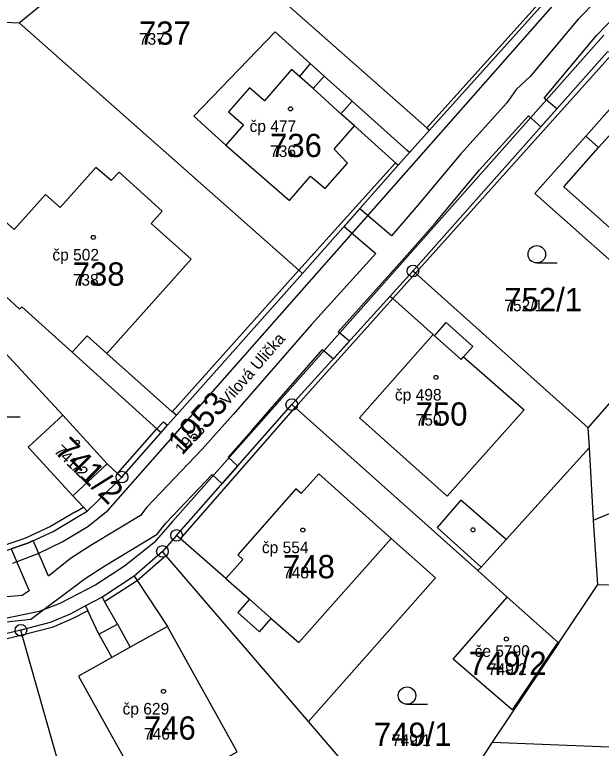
# Model space of a CAD drawing. Extents: x -763628 to -761565, y -976033 to -973833.
# Drawn here: x -762257.5 to -762207, y -974719.9 to -974656.7 of the extents above; entities that cross this region are included whole.
import ezdxf

# ---------------------------------------------------------------- set-up
doc = ezdxf.new("R2010")
doc.units = 0
for name, color, linetype in [('KN_cisla parcel 1000', 7, 'Continuous'), ('KN_cisla parcel 500', 7, 'Continuous'), ('KN_cisla popisna 500', 7, 'Continuous'), ('KN_hranice parcel', 7, 'Continuous'), ('KN_popisy', 7, 'Continuous'), ('KN_vecna bremena', 7, 'Continuous'), ('KN_vnitrni kresba parcel', 7, 'Continuous'), ('KN_znacky bodu BP', 7, 'Continuous'), ('KN_znacky budov', 7, 'Continuous'), ('KN_znacky kultur', 7, 'Continuous')]:
    doc.layers.add(name, color=color, linetype=linetype)

msp = doc.modelspace()

# ---------------------------------------------------------------- linework, layer by layer
at = {"layer": 'KN_hranice parcel'}
for p, q in [((-762257.09, -974657.45), (-762244.21, -974646.8)), ((-762262.51, -974657.17), (-762257.09, -974657.45)), ((-762223.51, -974668.61), (-762221.79, -974666.67)), ((-762224.46, -974669.69), (-762223.51, -974668.61)), ((-762232.71, -974679.01), (-762224.46, -974669.69)), ((-762243.56, -974691.22), (-762232.71, -974679.01)), ((-762208.11, -974692.29), (-762199.15, -974682.04)), ((-762243.54, -974701.56), (-762233.63, -974690.3)), ((-762248.24, -974696.54), (-762244.88, -974692.71)), ((-762207.28, -974705.78), (-762207.67, -974700.25)), ((-762243.54, -974701.56), (-762244.76, -974702.94)), ((-762210.64, -974710.82), (-762207.28, -974705.78)), ((-762207.28, -974705.78), (-762190.73, -974706.37)), ((-762215.08, -974706.87), (-762210.73, -974710.75)), ((-762210.64, -974710.82), (-762216.37, -974719.37)), ((-762210.73, -974710.75), (-762210.64, -974710.82)), ((-762222.55, -974728.78), (-762232.18, -974717.57)), ((-762216.37, -974719.37), (-762222.55, -974728.78))]:
    msp.add_line(p, q, dxfattribs=at)
for points in [[(-762221.79, -974666.67), (-762211.21, -974654.91), (-762212.34, -974651.01)], [(-762236.37, -974653.75), (-762222.01, -974666.48), (-762221.79, -974666.67)], [(-762257.09, -974657.45), (-762233.01, -974678.74), (-762232.71, -974679.01)], [(-762223.51, -974668.61), (-762223.73, -974668.41), (-762228.43, -974664.18), (-762230.84, -974662.02), (-762232.04, -974660.94), (-762235.06, -974658.22), (-762242.06, -974665.47), (-762239.3, -974667.96), (-762233.82, -974672.73), (-762232.01, -974670.63), (-762230.76, -974671.71), (-762228.82, -974669.51), (-762229.99, -974668.32), (-762228.23, -974666.3), (-762224.69, -974669.49), (-762224.46, -974669.69)], [(-762202.51, -974659.7), (-762206.5, -974659.96), (-762223.2, -974678.8)], [(-762202.51, -974659.7), (-762202.71, -974659.92), (-762203.96, -974661.32), (-762205.84, -974664.39), (-762208.32, -974667.18), (-762212.71, -974672.12), (-762202.76, -974680.97), (-762200.02, -974677.89)], [(-762243.56, -974691.22), (-762243.91, -974690.91), (-762249.55, -974685.91), (-762242.28, -974677.77), (-762245.72, -974674.71), (-762244.78, -974673.65), (-762248.49, -974670.3), (-762249.17, -974671.02), (-762250.48, -974669.9), (-762253.55, -974673.34), (-762254.82, -974672.21), (-762257.51, -974675.24), (-762260.52, -974672.57), (-762263.79, -974675.92), (-762260.66, -974678.79), (-762257.05, -974682.09), (-762256.85, -974681.88), (-762252.52, -974685.8), (-762245.23, -974692.4), (-762244.88, -974692.71)], [(-762273.2, -974675.16), (-762268.31, -974675.26), (-762267.98, -974675.4), (-762253.34, -974691.21)], [(-762223.2, -974678.8), (-762225.16, -974680.97), (-762233.63, -974690.3)], [(-762208.11, -974692.29), (-762222.97, -974679), (-762223.2, -974678.8)], [(-762207.67, -974700.25), (-762178.22, -974687.98), (-762177.79, -974687.84)], [(-762233.63, -974690.3), (-762233.33, -974690.56), (-762217.62, -974704.59), (-762215.08, -974706.87)], [(-762251.23, -974699.47), (-762251.56, -974699.12), (-762252.46, -974698.14), (-762256.32, -974693.97), (-762253.34, -974691.21)], [(-762253.34, -974691.21), (-762249.52, -974695.39), (-762248.63, -974696.22), (-762248.24, -974696.54)], [(-762244.88, -974692.71), (-762244.32, -974692.07), (-762243.56, -974691.22)], [(-762207.67, -974700.25), (-762208.01, -974694), (-762208.11, -974692.29)], [(-762232.18, -974717.57), (-762221.25, -974705.22), (-762225.07, -974701.83), (-762231.31, -974696.27), (-762232.81, -974697.95), (-762233.27, -974697.54), (-762238.28, -974703.23), (-762237.85, -974703.63), (-762239.31, -974705.27), (-762243.2, -974701.85), (-762243.54, -974701.56)], [(-762251.23, -974699.47), (-762250.26, -974698.54), (-762248.24, -974696.54)], [(-762274.8, -974704.07), (-762269.9, -974703.9), (-762268.41, -974703.84), (-762263.3, -974703.66), (-762260.93, -974703.38), (-762258.47, -974702.94), (-762256.33, -974702.23), (-762254.17, -974701.21), (-762252.01, -974699.93), (-762251.23, -974699.47)], [(-762244.76, -974702.94), (-762247.18, -974705.06), (-762249.63, -974706.69), (-762249.96, -974706.87), (-762251.37, -974707.63), (-762252.69, -974708.34), (-762254.43, -974709.06), (-762256.94, -974709.73)], [(-762232.18, -974717.57), (-762244.47, -974703.28), (-762244.76, -974702.94)], [(-762210.73, -974710.75), (-762214.65, -974716.57), (-762219.73, -974712.21), (-762215.08, -974706.87)], [(-762244.32, -974709.41), (-762247.53, -974711.19), (-762249.11, -974712.07), (-762251.98, -974713.67), (-762245.98, -974724.46), (-762238.32, -974720.18), (-762244.32, -974709.41)], [(-762256.94, -974709.73), (-762259.85, -974710.4), (-762261.07, -974710.45)], [(-762252.22, -974726.41), (-762256.82, -974710.15), (-762256.94, -974709.73)], [(-762216.37, -974719.37), (-762175.41, -974720.99), (-762174.98, -974721.01)]]:
    msp.add_lwpolyline(points, dxfattribs=at)
at = {"layer": 'KN_vecna bremena'}
for points in [[(-762207.35, -974655.42), (-762208.99, -974657.12), (-762213.1, -974662.05), (-762214.33, -974663.17), (-762215.13, -974664.33), (-762219.08, -974668.71), (-762222.91, -974673.31), (-762225.05, -974675.76), (-762227.78, -974673.44), (-762229.13, -974674.97), (-762226.4, -974677.28), (-762231.93, -974683.41), (-762238.68, -974691.14), (-762241.33, -974694.14), (-762246.09, -974699.13), (-762246.64, -974699.84), (-762250.83, -974702.37), (-762252.66, -974703.56), (-762254.56, -974705.07), (-762255.87, -974702.01), (-762256.33, -974702.23), (-762257.79, -974702.72), (-762256.24, -974706.32), (-762256.83, -974706.72), (-762265.28, -974707.45)], [(-762262.17, -974709.44), (-762256.09, -974708.78), (-762251.42, -974705.28), (-762249.71, -974704.17), (-762245.2, -974701.46), (-762244.47, -974700.51), (-762240.48, -974696.32), (-762239.63, -974697.12), (-762238.28, -974695.59), (-762239.1, -974694.82), (-762237.08, -974692.54), (-762230.99, -974685.56), (-762230.04, -974686.35), (-762228.67, -974684.83), (-762229.64, -974684.03), (-762224.12, -974677.91), (-762221.29, -974674.69), (-762217.48, -974670.09), (-762213.27, -974665.44), (-762212.19, -974666.38), (-762210.83, -974664.85), (-762211.9, -974663.93), (-762207.41, -974658.54), (-762205.76, -974656.82)]]:
    msp.add_lwpolyline(points, dxfattribs=at)
at = {"layer": 'KN_vnitrni kresba parcel'}
for p, q in [((-762249.43, -974699.39), (-762209.23, -974653.76)), ((-762222.01, -974666.48), (-762211.44, -974654.71)), ((-762206.76, -974658.49), (-762243.89, -974700.36)), ((-762222.97, -974679), (-762206.16, -974660.26)), ((-762232.04, -974660.94), (-762232.97, -974662.05)), ((-762233.65, -974661.44), (-762235.99, -974664.14)), ((-762232.97, -974662.05), (-762233.65, -974661.44)), ((-762231.8, -974663.1), (-762232.97, -974662.05)), ((-762230.84, -974662.02), (-762231.8, -974663.1)), ((-762237.26, -974663.04), (-762239.08, -974665.1)), ((-762235.99, -974664.14), (-762237.26, -974663.04)), ((-762229.4, -974665.26), (-762231.8, -974663.1)), ((-762229.4, -974665.26), (-762228.43, -974664.18)), ((-762239.08, -974665.1), (-762237.79, -974666.22)), ((-762228.23, -974666.3), (-762229.4, -974665.26)), ((-762207.22, -974668.17), (-762204.73, -974665.38)), ((-762237.79, -974666.22), (-762239.3, -974667.96)), ((-762207.22, -974668.17), (-762208.32, -974667.18)), ((-762210.23, -974671.55), (-762207.22, -974668.17)), ((-762233.01, -974678.74), (-762224.69, -974669.49)), ((-762202.2, -974678.69), (-762210.23, -974671.55)), ((-762243.91, -974690.91), (-762233.01, -974678.74)), ((-762224.92, -974681.18), (-762222.97, -974679)), ((-762233.33, -974690.56), (-762224.92, -974681.18)), ((-762225.16, -974680.97), (-762224.92, -974681.18)), ((-762224.92, -974681.18), (-762221.47, -974684.27)), ((-762221.36, -974684.37), (-762220.35, -974683.24)), ((-762220.35, -974683.24), (-762218.04, -974685.31)), ((-762227.8, -974691.44), (-762221.47, -974684.27)), ((-762221.47, -974684.27), (-762221.36, -974684.37)), ((-762219.06, -974686.43), (-762221.36, -974684.37)), ((-762252.52, -974685.8), (-762251.25, -974684.39)), ((-762251.25, -974684.39), (-762249.55, -974685.91)), ((-762218.84, -974686.19), (-762218.04, -974685.31)), ((-762219.06, -974686.43), (-762218.84, -974686.19)), ((-762218.84, -974686.19), (-762213.64, -974690.74)), ((-762243.2, -974701.85), (-762233.33, -974690.56)), ((-762213.64, -974690.74), (-762220.25, -974698.18)), ((-762245.23, -974692.4), (-762244.67, -974691.77)), ((-762244.67, -974691.77), (-762244.32, -974692.07)), ((-762220.25, -974698.18), (-762227.8, -974691.44)), ((-762248.63, -974696.22), (-762245.23, -974692.4)), ((-762215.19, -974701.91), (-762208.01, -974694)), ((-762252.46, -974698.14), (-762249.52, -974695.39)), ((-762219.08, -974698.54), (-762221.11, -974700.88)), ((-762215.19, -974701.91), (-762219.08, -974698.54)), ((-762252.25, -974699.52), (-762254.38, -974700.79)), ((-762252.25, -974699.52), (-762251.56, -974699.12)), ((-762251.17, -974700.79), (-762249.43, -974699.39)), ((-762254.38, -974700.79), (-762256.53, -974701.8)), ((-762253.32, -974702.08), (-762251.17, -974700.79)), ((-762243.89, -974700.36), (-762245.5, -974702.19)), ((-762221.11, -974700.88), (-762217.34, -974704.29)), ((-762256.53, -974701.8), (-762258.55, -974702.48)), ((-762233.03, -974710.79), (-762225.07, -974701.83)), ((-762217.34, -974704.29), (-762215.19, -974701.91)), ((-762255.44, -974703.13), (-762253.32, -974702.08)), ((-762245.5, -974702.19), (-762248.03, -974704.2)), ((-762257.63, -974703.94), (-762255.44, -974703.13)), ((-762246.94, -974705.43), (-762244.47, -974703.28)), ((-762248.03, -974704.2), (-762250.49, -974705.82)), ((-762217.62, -974704.59), (-762217.34, -974704.29)), ((-762247.18, -974705.06), (-762246.94, -974705.43)), ((-762250.49, -974705.82), (-762253.6, -974707.41)), ((-762249.74, -974707.26), (-762246.94, -974705.43)), ((-762246.94, -974705.43), (-762244.32, -974709.41)), ((-762239.31, -974705.27), (-762237.28, -974707.05)), ((-762249.96, -974706.87), (-762249.74, -974707.26)), ((-762237.28, -974707.05), (-762238.28, -974708.19)), ((-762235.41, -974708.7), (-762237.28, -974707.05)), ((-762253.6, -974707.41), (-762255.37, -974708.1)), ((-762251.37, -974707.63), (-762251.18, -974708.04)), ((-762248.64, -974709.19), (-762249.74, -974707.26)), ((-762255.37, -974708.1), (-762259.75, -974709.01)), ((-762251.18, -974708.04), (-762252.52, -974708.75)), ((-762250.23, -974710.07), (-762251.18, -974708.04)), ((-762238.28, -974708.19), (-762236.41, -974709.85)), ((-762252.52, -974708.75), (-762254.26, -974709.48)), ((-762236.41, -974709.85), (-762235.41, -974708.7)), ((-762235.41, -974708.7), (-762233.03, -974710.79)), ((-762254.26, -974709.48), (-762256.82, -974710.15)), ((-762250.23, -974710.07), (-762248.64, -974709.19)), ((-762248.64, -974709.19), (-762247.53, -974711.19)), ((-762256.82, -974710.15), (-762259.79, -974710.85)), ((-762250.23, -974710.07), (-762249.11, -974712.07))]:
    msp.add_line(p, q, dxfattribs=at)
at = {"layer": 'KN_znacky bodu BP'}
for centre, radius in [((-762223.2, -974678.8), 0.5), ((-762223.2, -974678.8), 0.0303), ((-762233.63, -974690.3), 0.5), ((-762233.63, -974690.3), 0.0303), ((-762248.24, -974696.54), 0.5), ((-762248.24, -974696.54), 0.0303), ((-762243.54, -974701.56), 0.5), ((-762243.54, -974701.56), 0.0303), ((-762244.76, -974702.94), 0.5), ((-762244.76, -974702.94), 0.0303), ((-762256.94, -974709.73), 0.5), ((-762256.94, -974709.73), 0.0303)]:
    msp.add_circle(centre, radius, dxfattribs=at)
at = {"layer": 'KN_znacky budov'}
for centre in [(-762233.737, -974664.839), (-762250.707, -974675.909), (-762221.227, -974687.959), (-762252.087, -974693.549), (-762232.677, -974701.099), (-762218.037, -974701.079), (-762215.157, -974710.479), (-762244.667, -974714.989)]:
    msp.add_circle(centre, 0.175, dxfattribs=at)
at = {"layer": 'KN_znacky kultur'}
for p, q in [((-762212.543, -974678.11), (-762210.793, -974678.11)), ((-762258.753, -974691.36), (-762257.003, -974691.36)), ((-762223.713, -974716.1), (-762221.963, -974716.1))]:
    msp.add_line(p, q, dxfattribs=at)
for centre in [(-762212.543, -974677.36), (-762223.713, -974715.35)]:
    msp.add_circle(centre, 0.75, dxfattribs=at)

# ---------------------------------------------------------------- texts
at = {"layer": 'KN_cisla parcel 1000'}
for s, p in [('737', (-762246.78, -974659.32)), ('736', (-762235.5, -974668.99)), ('738', (-762252.48, -974680.06)), ('752/1', (-762215.34, -974682.26)), ('750', (-762222.97, -974692.11)), ('748', (-762234.38, -974705.25)), ('749/2', (-762218.398, -974713.567)), ('746', (-762246.35, -974719.14)), ('749/1', (-762226.563, -974719.68))]:
    msp.add_text(s, height=2, dxfattribs=at).set_placement(p)
for s, rotation, p in [('1953', 47, (-762243.045, -974694.691)), ('741/2', 316, (-762254.151, -974694.371))]:
    msp.add_text(s, height=2, rotation=rotation, dxfattribs=at).set_placement(p)
at = {"layer": 'KN_cisla parcel 500'}
for s, p in [('737', (-762246.78, -974659.32)), ('736', (-762235.5, -974668.99)), ('738', (-762252.48, -974680.06)), ('752/1', (-762215.34, -974682.26)), ('750', (-762222.97, -974692.11)), ('748', (-762234.38, -974705.25)), ('749/2', (-762216.748, -974713.567)), ('746', (-762246.35, -974719.14)), ('749/1', (-762225.013, -974719.68))]:
    msp.add_text(s, height=1, dxfattribs=at).set_placement(p)
for s, rotation, p in [('1953', 47, (-762243.045, -974694.691)), ('741/2', 316, (-762254.151, -974694.371))]:
    msp.add_text(s, height=1, rotation=rotation, dxfattribs=at).set_placement(p)
at = {"layer": 'KN_cisla popisna 500'}
for s, p in [('čp 477', (-762237.261, -974666.831)), ('čp 502', (-762254.231, -974677.901)), ('čp 498', (-762224.751, -974689.951)), ('čp 554', (-762236.201, -974703.091)), ('če 5790', (-762217.899, -974712.016)), ('čp 629', (-762248.191, -974716.981))]:
    msp.add_text(s, height=1, dxfattribs=at).set_placement(p)
at = {"layer": 'KN_popisy'}
msp.add_text('Vilová Ulička', height=1, rotation=49, dxfattribs=at).set_placement((-762239.151, -974690.445))

doc.saveas('drawing.dxf')
